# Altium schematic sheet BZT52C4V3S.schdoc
size 127 x 101 mm
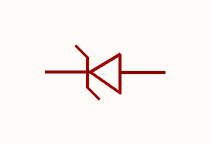
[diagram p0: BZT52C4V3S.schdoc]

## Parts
ZD?  bzt52c4v3s_c22610  [SOD-323_L1.8-W1.3-LS2.5-RD]  (value not drawn)

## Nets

Not connected (* = marked no-connect by the designer): ZD? 1(K) 2(A)

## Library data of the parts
ZD? = bzt52c4v3s_c22610: 二极管配置:1个独立式;稳压值(标称值):4.3V;稳压值(范围):4V~4.6V;耗散功率(Pd):200mW;; Manufacturer: CJ(江苏长电/长晶); AddInBom: yes; ModelId: db63db13d9e342eb939127d413d6200b; ModelTransform: 104.3305,51.181,0,0,0,0,0,-0.004,0; Diode Configuration: 1个独立式; Zener Voltage(Nom): 4.3V; Reverse Leakage Current (Ir): 3uA@1V; Pd - Power Dissipation: 200mW; Impedance(Zzt): 90Ω; Impedance(Zzk): 600Ω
